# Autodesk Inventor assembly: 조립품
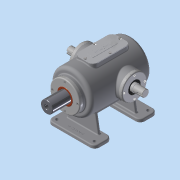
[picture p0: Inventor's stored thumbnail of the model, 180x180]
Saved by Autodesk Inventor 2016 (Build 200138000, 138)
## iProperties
Created: 2018-11
Part Number: 조립품
Material: 일반
Document SubType Name: Assembly
Designer: user
Author: user
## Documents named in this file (15)
- C:\Users\user\Desktop\381121V1007\조립품.iam
- C:\Users\user\Desktop\381121V1007\가변스프링.ipt
- C:\Users\user\Desktop\381121V1007\베어링 6205.ipt
- 베어링 6205.ipt
- C:\Users\user\Desktop\381121V1007\본체.ipt
- C:\Users\user\Desktop\381121V1007\볼트 M4x0.7.ipt
- C:\Users\user\Desktop\381121V1007\부시.ipt
- C:\Users\user\Desktop\381121V1007\상부커버.ipt
- C:\Users\user\Desktop\381121V1007\슬라이드 커버.ipt
- C:\Users\user\Desktop\381121V1007\슬라이드.ipt
- C:\Users\user\Desktop\381121V1007\오일실.ipt
- 오일실.ipt
- C:\Users\user\Desktop\381121V1007\육각머리볼트 M4.ipt
- C:\Users\user\Desktop\381121V1007\축 커버.ipt
- C:\Users\user\Desktop\381121V1007\편심축.ipt
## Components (13 placed, 2 different names)
1. 가변스프링:1
2. M4x0.7:1
3. M4x0.7:4
4. M4x0.7:5
5. M4x0.7:6
6. M4x0.7:3
7. M4x0.7:7
8. M4x0.7:8
9. M4x0.7:9
10. M4x0.7:2
11. M4x0.7:10
12. M4x0.7:11
13. M4x0.7:12
